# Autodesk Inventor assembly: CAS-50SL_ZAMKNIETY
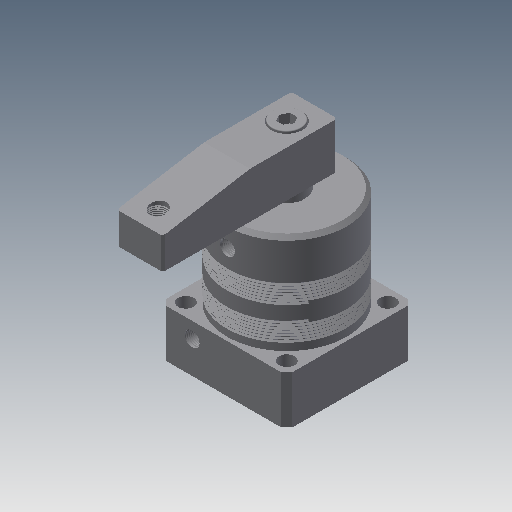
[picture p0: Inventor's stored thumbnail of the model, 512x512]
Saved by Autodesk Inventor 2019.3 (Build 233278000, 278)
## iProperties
Created: 2009-09
Part Number: CAS-50SL_ZAMKNIETY
Material: Ogólny
Document SubType Name: Assembly
Designer: CADENGINEERING4
Sending System: PRO/ENGINEER BY PARAMETRIC TECHNOLOGY CORPORATION, 2007170
Preprocessor: PRO/ENGINEER BY PARAMETRIC TECHNOLOGY CORPORATION, 2007170
Title: CAS-50S_ASM
Author: Administrator
Revision Number: 1LAST_VERSION
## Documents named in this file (7)
- D:\Vault_2016\Projekty\STRONA\Pneumatic\Line ; Pipe connecct - type\cas-50s_asm\CAS-50SL_ZAMKNIETY.iam
- D:\Vault_2016\Projekty\STRONA\Pneumatic\Line ; Pipe connecct - type\cas-50s_asm\CAS-50BT.ipt
- D:\Vault_2016\Projekty\STRONA\Pneumatic\Line ; Pipe connecct - type\cas-50s_asm\CAS-50SHSG.ipt
- D:\Vault_2016\Projekty\STRONA\Pneumatic\Line ; Pipe connecct - type\cas-50s_asm\CAS-50HG.ipt
- D:\Vault_2016\Projekty\STRONA\Pneumatic\Line ; Pipe connecct - type\cas-50s_asm\M4.ipt
- D:\Vault_2016\Projekty\STRONA\Pneumatic\Line ; Pipe connecct - type\cas-50s_asm\CAS-50SYB.ipt
- D:\Vault_2016\Projekty\STRONA\Pneumatic\Line ; Pipe connecct - type\cas-50s_asm\M10LC.ipt
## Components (9 placed, 9 different names)
1. CAS-50BT_0 — Zestawiające:5, Kątowe:1, Równoległe:1
2. CAS-50SHSG_1 — Zestawiające:1, Zestawiające:2, Zestawiające:4, Zestawiające:5
3. CAS-50HG_2
4. M4_3
5. M4_4
6. M4_5
7. M4_6
8. CAS-50SYB_7 — Zestawiające:1, Zestawiające:3, Zestawiające:4, Kątowe:1, Równoległe:1
9. M10LC_8 — Zestawiające:2, Zestawiające:3
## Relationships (7: Mate 5, Angle 1, Flush 1)
- Zestawiające:1 [Mate]: CAS-50SHSG_1 ↔ CAS-50SYB_7
- Zestawiające:2 [Mate]: CAS-50SHSG_1 ↔ M10LC_8
- Zestawiające:3 [Mate]: CAS-50SYB_7 ↔ M10LC_8
- Zestawiające:4 [Mate]: CAS-50SHSG_1 ↔ CAS-50SYB_7
- Zestawiające:5 [Mate]: CAS-50BT_0 ↔ CAS-50SHSG_1
- Kątowe:1 [Angle]: CAS-50BT_0 ↔ CAS-50SYB_7
- Równoległe:1 [Flush]: CAS-50BT_0 ↔ CAS-50SYB_7
